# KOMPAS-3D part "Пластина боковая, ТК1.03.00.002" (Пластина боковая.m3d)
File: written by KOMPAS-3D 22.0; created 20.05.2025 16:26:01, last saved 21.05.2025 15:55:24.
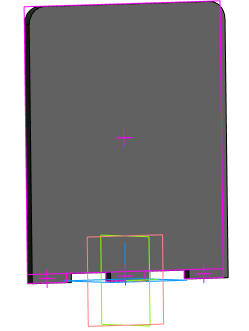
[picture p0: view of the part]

Document properties: Автор: TC; Полное имя файла: Пластина боковая.cdw

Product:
- Part/product: Пластина боковая  | designation ТК1.03.00.002
    Материал: Сталь 09Г2С ГОСТ 19281-2014 (density 7850 kg/m3)
    Масса: 0.778998
    Форматы листов документа: A4

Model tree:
1. Эскиз:1
2. Элемент выдавливания:1
     Расстояние 1 = 5
3. Скругление:1  (with: Элемент выдавливания:1)  (labels: Сталь 09Г2С ГОСТ 19281-2014; BOSimple***Material:4ccf0190-16b6-4223-9222-aa108d28a442)
     Радиус = 10

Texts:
  ТК1.03.00.002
